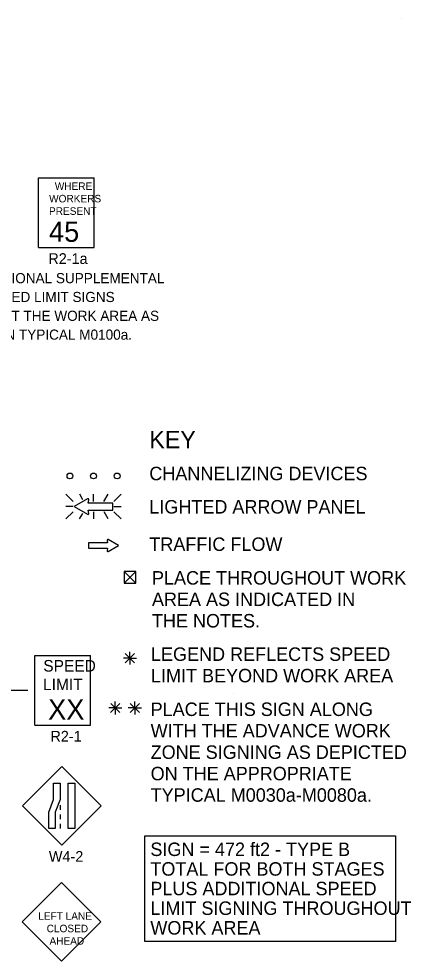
# Model space of a CAD drawing. Extents: x 16590 to 19504, y 5703 to 6974.
# Drawn here: x 17159 to 17430, y 6280 to 6931 of the extents above; entities that cross this region are included whole.
import ezdxf

# ---------------------------------------------------------------- set-up
doc = ezdxf.new("R2010")
doc.units = 0
for name, color, linetype in [('BORDER', 7, 'Continuous'), ('MT_SCRATCH_LEVEL_E', 7, 'Continuous'), ('TRAFFIC_SIGNS_PR', 7, 'Continuous'), ('TYPICAL_TEXT_DIMEN_EX', 7, 'Continuous'), ('TYPICAL_TEXT_DIMEN_PR', 7, 'Continuous')]:
    doc.layers.add(name, color=color, linetype=linetype)

msp = doc.modelspace()

# ---------------------------------------------------------------- linework, layer by layer
at = {"layer": 'BORDER'}
msp.add_line((17423.55, 6930.8), (17423.55, 6930.8), dxfattribs=at)
at = {"layer": 'MT_SCRATCH_LEVEL_E'}
for p, q in [((17220.19, 6570.81), (17220.5, 6569.04)), ((17228.11, 6567.19), (17220.87, 6571.3)), ((17220.5, 6569.04), (17207.24, 6569.04)), ((17207.24, 6569.04), (17207.24, 6565.3)), ((17207.24, 6565.3), (17220.5, 6565.3)), ((17220.5, 6565.3), (17220.19, 6563.52)), ((17220.87, 6563.04), (17228.11, 6567.19))]:
    msp.add_line(p, q, dxfattribs=at)
for centre, start, end in [((17220.64, 6570.89), 60.42484, 189.96381), ((17220.65, 6563.45), 170.03619, 299.77312)]:
    msp.add_arc(centre, 0.463, start, end, dxfattribs=at)
at = {"layer": 'TRAFFIC_SIGNS_PR'}
for p, q in [((17172.76, 6821.01), (17211.16, 6821.01)), ((17172.76, 6773.01), (17172.76, 6821.01)), ((17211.16, 6773.01), (17211.16, 6821.01)), ((17172.76, 6773.01), (17211.16, 6773.01)), ((17191.69, 6602.61), (17196.63, 6597.68)), ((17203.46, 6598.79), (17201.25, 6602.62)), ((17210.78, 6597.68), (17210.78, 6602.62)), ((17218.01, 6597.68), (17220.86, 6602.62)), ((17224.93, 6597.68), (17229.86, 6602.62)), ((17196.63, 6594.12), (17191.69, 6594.12)), ((17191.69, 6585.64), (17196.63, 6590.57)), ((17210.78, 6590.57), (17210.78, 6585.63)), ((17220.91, 6585.63), (17218.06, 6590.57)), ((17224.93, 6594.12), (17229.86, 6594.12)), ((17224.93, 6590.57), (17229.86, 6585.63)), ((17201.21, 6585.63), (17203.32, 6589.3)), ((17170.33, 6491.35), (17208.78, 6491.35)), ((17170.33, 6443.29), (17170.33, 6491.35)), ((17208.78, 6443.29), (17208.78, 6491.35)), ((17170.33, 6443.29), (17208.78, 6443.29)), ((17189.01, 6414.62), (17161.85, 6387.47)), ((17216.16, 6387.47), (17189.01, 6414.62)), ((17187.76, 6387.96), (17187.76, 6384.76)), ((17161.85, 6387.47), (17189.01, 6360.32)), ((17187.76, 6381.56), (17187.76, 6378.36)), ((17189.01, 6360.32), (17216.16, 6387.47)), ((17187.76, 6375.16), (17187.76, 6371.96)), ((17188.75, 6334.62), (17161.6, 6307.47)), ((17215.9, 6307.47), (17188.75, 6334.62)), ((17161.6, 6307.47), (17188.75, 6280.31)), ((17188.75, 6280.31), (17215.9, 6307.47))]:
    msp.add_line(p, q, dxfattribs=at)
for points in [[(17206.7, 6599.4), (17197.41, 6594.12), (17206.71, 6588.8)], [(17207.58, 6589.43), (17207.18, 6591.7), (17224.19, 6591.7), (17224.19, 6596.5), (17207.18, 6596.5), (17207.58, 6598.78)]]:
    msp.add_lwpolyline(points, dxfattribs=at)
for points in [[(17187.76, 6403.2), (17187.76, 6392.02), (17184.42, 6383.14), (17184.42, 6371.96), (17179.92, 6371.96), (17179.92, 6383.14), (17183.27, 6392.02), (17183.27, 6403.2)], [(17197.9, 6403.2), (17197.9, 6371.96), (17193.4, 6371.96), (17193.4, 6403.2)]]:
    msp.add_lwpolyline(points, close=True, dxfattribs=at)
for centre in [(17194.49, 6615.24), (17210.79, 6615.24), (17227.09, 6615.24)]:
    msp.add_circle(centre, 2, dxfattribs=at)
for centre, radius, start, end in [((17206.99, 6598.88), 0.598, 350.73078, 118.89165), ((17206.99, 6589.33), 0.597, 241.48329, 9.95933)]:
    msp.add_arc(centre, radius, start, end, dxfattribs=at)
at = {"layer": 'TYPICAL_TEXT_DIMEN_EX'}
msp.add_lwpolyline([(17246.32, 6366.75), (17419.3, 6366.75), (17419.3, 6293.88), (17246.32, 6293.88)], close=True, dxfattribs=at)
at = {"layer": 'TYPICAL_TEXT_DIMEN_PR'}
for p, q in [((17231.96, 6549.26), (17239.96, 6541.26)), ((17231.96, 6541.26), (17239.96, 6549.26)), ((17232.74, 6492.68), (17239.11, 6486.3)), ((17239.11, 6492.68), (17232.74, 6486.3)), ((17235.92, 6489.49), (17235.92, 6493.94)), ((17235.92, 6489.49), (17231.39, 6489.49)), ((17235.92, 6489.49), (17239.11, 6489.49)), ((17235.92, 6489.49), (17240.4, 6489.49)), ((17235.92, 6489.49), (17235.92, 6484.99)), ((17070.33, 6467.47), (17165.43, 6467.47)), ((17225.82, 6455.09), (17225.82, 6459.54)), ((17239.33, 6455.09), (17239.33, 6459.54)), ((17225.82, 6455.09), (17221.29, 6455.09)), ((17229.01, 6458.28), (17222.63, 6451.9)), ((17222.64, 6458.28), (17229.01, 6451.9)), ((17225.82, 6455.09), (17229.01, 6455.09)), ((17225.82, 6455.09), (17230.3, 6455.09)), ((17225.82, 6455.09), (17225.82, 6450.59)), ((17239.33, 6455.09), (17234.8, 6455.09)), ((17236.14, 6458.28), (17242.52, 6451.9)), ((17242.52, 6458.28), (17236.14, 6451.9)), ((17239.33, 6455.09), (17242.52, 6455.09)), ((17239.33, 6455.09), (17243.81, 6455.09)), ((17239.33, 6455.09), (17239.33, 6450.59))]:
    msp.add_line(p, q, dxfattribs=at)
msp.add_lwpolyline([(17231.96, 6549.26), (17231.96, 6541.26), (17239.96, 6541.26), (17239.96, 6549.26)], close=True, dxfattribs=at)
msp.add_open_spline([(17307.58, 6464.91), (17307.6, 6464.91), (17307.61, 6464.91), (17307.61, 6464.91)], degree=2, dxfattribs=at)

# ---------------------------------------------------------------- texts
at = {"layer": 'TRAFFIC_SIGNS_PR'}
for s, height, p in [('WHERE', 5.2, (17184.07, 6812.7)), ('WORKERS', 5.2, (17180.14, 6804.1)), ('PRESENT', 5.2, (17180.07, 6795.5)), ('45', 14.031, (17180.06, 6776.87)), ('R2-1a', 7.44, (17179.61, 6761.57)), ('PLACE ADDITIONAL SUPPLEMENTAL', 7, (17092.76, 6748.31)), ('SETS OF SPEED LIMIT SIGNS', 7, (17092.76, 6735.31)), ('THROUGHOUT THE WORK AREA AS', 7, (17092.76, 6722.31)), ('DEPICTED ON TYPICAL M0100a.', 7, (17092.76, 6709.31)), ('SPEED', 8.01, (17176.1, 6480.2)), ('LIMIT', 8.01, (17175.94, 6467.38)), ('XX', 14.048, (17179.45, 6447.05)), ('R2-1', 7.449, (17181.02, 6431.84)), ('W4-2', 7.44, (17179.96, 6348.88)), ('LEFT LANE', 5.2, (17172.63, 6308.86)), ('CLOSED', 5.2, (17178.46, 6300.26)), ('AHEAD', 5.2, (17180.41, 6291.66))]:
    msp.add_text(s, height=height, dxfattribs=at).set_placement(p)
at = {"layer": 'TYPICAL_TEXT_DIMEN_EX'}
for s, height, p in [('KEY', 12, (17249.32, 6634.35)), ('CHANNELIZING DEVICES', 9.3, (17249.32, 6612.3)), ('LIGHTED ARROW PANEL', 9.3, (17249.32, 6589.3)), ('TRAFFIC FLOW', 9.3, (17249.32, 6563.5)), ('PLACE THROUGHOUT WORK', 9.3, (17251.14, 6540.25)), ('AREA AS INDICATED IN', 9.3, (17251.14, 6525.45)), ('THE NOTES.', 9.3, (17251.14, 6510.65)), ('LEGEND REFLECTS SPEED', 9.3, (17250.47, 6487.59)), ('LIMIT BEYOND WORK AREA', 9.3, (17250.47, 6472.79)), ('PLACE THIS SIGN ALONG', 9.3, (17250.23, 6449.55)), ('WITH THE ADVANCE WORK', 9.3, (17250.23, 6434.75)), ('ZONE SIGNING AS DEPICTED', 9.3, (17250.23, 6419.95)), ('ON THE APPROPRIATE', 9.3, (17250.23, 6405.15)), ('TYPICAL M0030a-M0080a.', 9.3, (17250.23, 6390.35)), ('SIGN = 472 ft2 - TYPE B', 9.3, (17250.04, 6352.88)), ('TOTAL FOR BOTH STAGES', 9.3, (17250.04, 6339.33)), ('PLUS ADDITIONAL SPEED', 9.3, (17250.04, 6325.78)), ('LIMIT SIGNING THROUGHOUT', 9.3, (17250.04, 6312.23)), ('WORK AREA', 9.3, (17250.04, 6298.68))]:
    msp.add_text(s, height=height, dxfattribs=at).set_placement(p)

doc.saveas('drawing.dxf')
